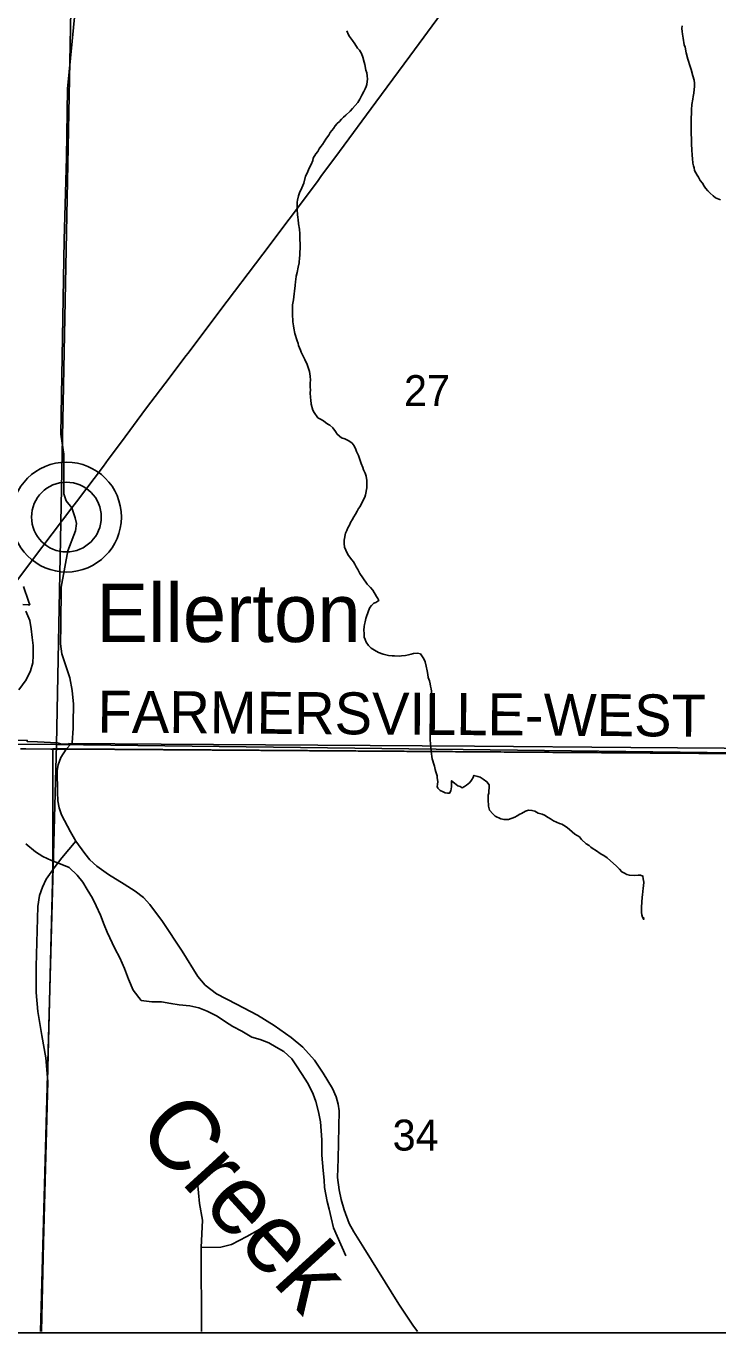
# Model space of a CAD drawing. Extents: x 0 to 34, y 0 to 22.
# Drawn here: x 2.988 to 3.924, y 14 to 15.768 of the extents above; entities that cross this region are included whole.
import ezdxf

# ---------------------------------------------------------------- set-up
doc = ezdxf.new("R2010")
doc.units = 0
for name, color, linetype in [('GM_X_County_Road', 7, 'Continuous'), ('GM_X_County_Road_Text', 7, 'Continuous'), ('GM_X_Interchange_Ramps', 7, 'Continuous'), ('GM_X_Interstate_Route', 7, 'Continuous'), ('GM_X_Minor_River', 7, 'Continuous'), ('GM_X_Minor_River_Text', 7, 'Continuous'), ('GM_X_Section', 7, 'Continuous'), ('GM_X_Section_Text', 7, 'Continuous'), ('GM_X_State_Route', 7, 'Continuous'), ('GM_X_State_Shield', 7, 'Continuous'), ('GM_X_Township_Road', 7, 'Continuous'), ('GM_X_Unincorporated', 7, 'Continuous'), ('GM_X_Unincorporated_Location', 7, 'Continuous'), ('GM_X_Unincorporated_Text', 7, 'Continuous'), ('SH_Data', 7, 'Continuous')]:
    doc.layers.add(name, color=color, linetype=linetype)

msp = doc.modelspace()

# ---------------------------------------------------------------- linework, layer by layer
at = {"layer": 'GM_X_County_Road'}
for p, q in [((3.042, 14.7898), (3.0487, 14.797)), ((3.042, 14.7898), (4.0225, 14.783)), ((3.0084, 14.0019), (3.0115, 14.1223))]:
    msp.add_line(p, q, dxfattribs=at)
for points in [[(3.0365, 15.2041), (3.0346, 15.2161), (3.0374, 15.3737), (3.0394, 15.4793), (3.0423, 15.5906), (3.0436, 15.6833), (3.0543, 15.7893), (3.0548, 15.7993)], [(3.0497, 15.1165), (3.042, 15.1261), (3.0389, 15.1356), (3.0389, 15.1892), (3.0365, 15.2041)], [(3.0487, 14.797), (3.05, 14.7984), (3.0515, 14.8181), (3.0516, 14.8251), (3.0519, 14.8508), (3.0503, 14.8692), (3.0469, 14.8864), (3.0363, 14.9191), (3.0351, 14.9255), (3.0345, 14.9323), (3.0348, 14.9583), (3.0352, 15.0093), (3.0444, 15.0583), (3.0547, 15.0852), (3.0558, 15.0952), (3.054, 15.1031), (3.0497, 15.1165)], [(2.9802, 14.7905), (2.9873, 14.7903), (3.0212, 14.7899)], [(3.0212, 14.7899), (3.0242, 14.7899), (3.042, 14.7898)], [(3.0237, 14.6266), (3.0243, 14.6275), (3.0362, 14.643), (3.0549, 14.6653), (3.0478, 14.6779), (3.0356, 14.7011), (3.0323, 14.7106), (3.0309, 14.72), (3.0303, 14.7319), (3.0296, 14.7609), (3.0312, 14.7688), (3.0347, 14.7784), (3.042, 14.7898)], [(3.0115, 14.1223), (3.017, 14.34), (3.0143, 14.3722), (3.0092, 14.4025), (3.0035, 14.435), (3.0012, 14.4605), (3.0015, 14.496), (3.0037, 14.5769), (3.0057, 14.5919), (3.0101, 14.603), (3.015, 14.6139), (3.0237, 14.6266)]]:
    msp.add_lwpolyline(points, dxfattribs=at)
at = {"layer": 'GM_X_Interchange_Ramps'}
for points in [[(2.9842, 15.0102), (2.9911, 14.99), (2.9927, 14.9853), (2.9907, 14.9854), (2.9835, 14.9857)], [(2.9612, 14.8022), (2.9892, 14.8018), (2.9891, 14.8003), (3.0033, 14.8), (3.0297, 14.7986), (3.0297, 14.7986), (3.036, 14.7967), (3.0455, 14.7966), (3.0457, 14.7976), (3.1707, 14.7967), (3.3824, 14.7952), (3.5947, 14.7938), (3.8063, 14.7923), (3.9957, 14.791)]]:
    msp.add_lwpolyline(points, dxfattribs=at)
at = {"layer": 'GM_X_Interstate_Route'}
for points in [[(4.0223, 14.7835), (3.0418, 14.7903), (3.024, 14.7904), (3.0241, 14.628), (3.0168, 14.3406), (3.0082, 14.0019)], [(3.0082, 14.0019), (3.0168, 14.3406), (3.0241, 14.628), (3.024, 14.7904), (3.0418, 14.7903), (4.0223, 14.7835)]]:
    msp.add_lwpolyline(points, dxfattribs=at)
at = {"layer": 'GM_X_Minor_River'}
for points in [[(3.4217, 15.7618), (3.4242, 15.7568), (3.4256, 15.7541), (3.4297, 15.7487), (3.4326, 15.7444), (3.4363, 15.7386), (3.4389, 15.7359), (3.4418, 15.7312), (3.4436, 15.7262), (3.4453, 15.7197), (3.446, 15.7163), (3.4477, 15.7086), (3.4488, 15.7052), (3.4494, 15.7013), (3.4497, 15.6964), (3.4492, 15.6933), (3.4488, 15.6895), (3.4479, 15.6865), (3.4467, 15.6835), (3.4447, 15.6797), (3.4423, 15.6748), (3.4395, 15.6696), (3.4367, 15.6651), (3.4296, 15.6568), (3.4265, 15.6535), (3.4206, 15.6479), (3.4175, 15.6453), (3.4148, 15.6423), (3.412, 15.6394), (3.4089, 15.6364), (3.4061, 15.6334), (3.4038, 15.63), (3.4014, 15.627), (3.3994, 15.6244), (3.3974, 15.621), (3.3955, 15.6184), (3.3935, 15.6154), (3.3911, 15.6117), (3.3887, 15.6083), (3.3867, 15.6053), (3.3844, 15.6023), (3.3824, 15.5989), (3.38, 15.5956), (3.3764, 15.5899), (3.3756, 15.5865), (3.3735, 15.5812), (3.3711, 15.5771), (3.3675, 15.5684), (3.3659, 15.5654), (3.3637, 15.5559), (3.3621, 15.5525), (3.3597, 15.5465), (3.3581, 15.5439), (3.3564, 15.5386), (3.3551, 15.5329), (3.3547, 15.5302), (3.3544, 15.5196), (3.355, 15.5135), (3.3557, 15.5093), (3.356, 15.5066), (3.3566, 15.5008), (3.3579, 15.4936), (3.3581, 15.4871), (3.3584, 15.4837), (3.3584, 15.481), (3.3585, 15.4726), (3.3581, 15.4577), (3.3577, 15.4551), (3.3571, 15.4479), (3.3558, 15.4422), (3.3545, 15.435), (3.3532, 15.43), (3.3527, 15.4255), (3.3523, 15.4228), (3.3518, 15.4175), (3.3512, 15.4099), (3.3507, 15.4061), (3.3497, 15.3981), (3.3484, 15.3913), (3.3481, 15.3791), (3.3489, 15.368), (3.3496, 15.3627), (3.3499, 15.3596), (3.3516, 15.3523), (3.3544, 15.3427), (3.3558, 15.3389), (3.3565, 15.3362), (3.359, 15.3297), (3.3601, 15.327), (3.363, 15.3208), (3.3652, 15.3173), (3.368, 15.3104), (3.3712, 15.3012), (3.3722, 15.2947), (3.3725, 15.2893), (3.3724, 15.2855), (3.3722, 15.2802), (3.3725, 15.2756), (3.3724, 15.2726), (3.3726, 15.2653), (3.3729, 15.2627)], [(3.8755, 15.7687), (3.8754, 15.7653), (3.8757, 15.7611), (3.8759, 15.7573), (3.8769, 15.7519), (3.8782, 15.7431), (3.8797, 15.7397), (3.881, 15.732), (3.8835, 15.7236), (3.8866, 15.7136), (3.888, 15.7097), (3.8901, 15.7013), (3.8919, 15.6951), (3.8925, 15.6913), (3.8924, 15.6871), (3.8914, 15.6776), (3.8905, 15.6731), (3.8901, 15.6697), (3.8887, 15.6624), (3.8882, 15.6552), (3.8878, 15.6392), (3.8879, 15.6316), (3.8879, 15.6289), (3.888, 15.6205), (3.8883, 15.6179), (3.8885, 15.611), (3.8885, 15.6083), (3.8887, 15.6015), (3.8892, 15.5931), (3.8895, 15.5892), (3.8901, 15.5828), (3.8908, 15.5793), (3.8918, 15.5766), (3.8925, 15.5728), (3.8962, 15.5666), (3.8976, 15.5639), (3.9002, 15.5596), (3.9031, 15.5558), (3.9053, 15.5519), (3.9071, 15.5492), (3.9105, 15.5453), (3.9134, 15.5422), (3.9176, 15.5386), (3.9209, 15.5359), (3.9277, 15.5331)], [(3.3729, 15.2627), (3.3735, 15.2569), (3.3756, 15.2485), (3.3774, 15.2454), (3.3826, 15.2384), (3.3863, 15.2364), (3.3901, 15.234), (3.3931, 15.2321), (3.3961, 15.2297), (3.3987, 15.2285), (3.4028, 15.2246), (3.4065, 15.2199), (3.4087, 15.2164), (3.4146, 15.211), (3.4192, 15.2097), (3.4245, 15.2073), (3.429, 15.2041), (3.4319, 15.2002), (3.4341, 15.1956), (3.4351, 15.1929), (3.4377, 15.1871), (3.4412, 15.1764), (3.4437, 15.171), (3.4444, 15.1679), (3.4466, 15.1633), (3.448, 15.1595), (3.449, 15.1537), (3.4487, 15.1434), (3.447, 15.1343), (3.4461, 15.1309), (3.4441, 15.1268), (3.4397, 15.1185), (3.4377, 15.1155), (3.4357, 15.1121), (3.4337, 15.108), (3.4313, 15.1042), (3.4289, 15.1001), (3.4269, 15.0967), (3.4253, 15.093), (3.4233, 15.0892), (3.4217, 15.0858), (3.4201, 15.082), (3.4183, 15.0729), (3.4182, 15.068), (3.4185, 15.0634), (3.4203, 15.0592), (3.4224, 15.0553), (3.4243, 15.0522), (3.4287, 15.046), (3.4309, 15.0433), (3.4327, 15.0402), (3.4345, 15.0367), (3.4367, 15.0329), (3.4396, 15.0278), (3.4433, 15.0216), (3.4492, 15.0131), (3.454, 15.0088), (3.457, 15.0049), (3.4621, 14.9964), (3.4639, 14.9937), (3.465, 14.991), (3.4611, 14.9884), (3.4584, 14.9874), (3.4553, 14.9844), (3.4529, 14.9814), (3.4513, 14.9769), (3.4476, 14.9667), (3.4467, 14.9621), (3.4459, 14.9587), (3.4454, 14.9557), (3.4449, 14.9511), (3.4452, 14.9465), (3.4454, 14.9416), (3.4465, 14.9381), (3.4479, 14.9347), (3.4512, 14.9304), (3.4549, 14.9265), (3.4591, 14.9237), (3.4647, 14.9209), (3.4711, 14.9185), (3.4783, 14.9168), (3.4833, 14.9163), (3.4863, 14.9162), (3.4928, 14.9157), (3.4958, 14.916), (3.5012, 14.9166), (3.5054, 14.9176), (3.5089, 14.9183), (3.5119, 14.9194), (3.5173, 14.92), (3.5215, 14.9191), (3.5259, 14.9122), (3.5277, 14.9083), (3.529, 14.9022), (3.5304, 14.8961), (3.5314, 14.8911), (3.5321, 14.8869), (3.5335, 14.8823), (3.5345, 14.8781), (3.5352, 14.875), (3.5359, 14.8716)], [(2.978, 14.87), (2.9879, 14.8838), (2.9939, 14.8958), (2.9969, 14.9068), (2.9975, 14.9166), (2.9971, 14.93), (2.9959, 14.941), (2.9947, 14.9528), (2.9927, 14.9639), (2.9874, 14.9766)], [(3.5359, 14.8716), (3.5362, 14.8685), (3.5364, 14.8624), (3.5362, 14.8555), (3.5357, 14.8517), (3.5354, 14.8392), (3.5353, 14.8361), (3.5349, 14.8331), (3.5344, 14.8156), (3.5347, 14.811), (3.5345, 14.8057), (3.5348, 14.8022), (3.5354, 14.7931), (3.536, 14.7866), (3.5363, 14.7835), (3.5369, 14.7801), (3.5372, 14.7767), (3.5383, 14.774), (3.539, 14.7709), (3.5404, 14.7671), (3.5414, 14.7625), (3.5425, 14.759), (3.5439, 14.7536), (3.5442, 14.751), (3.5448, 14.746), (3.5447, 14.7422), (3.5443, 14.7395), (3.545, 14.7369), (3.5483, 14.7341), (3.5521, 14.7321), (3.5551, 14.7309), (3.5581, 14.7304), (3.5608, 14.7304), (3.5628, 14.7334), (3.5633, 14.7391), (3.5635, 14.7471), (3.5676, 14.7439), (3.5721, 14.7404), (3.5751, 14.7392), (3.5781, 14.7376), (3.5812, 14.7394), (3.584, 14.7412), (3.5882, 14.7446), (3.5906, 14.7479), (3.5926, 14.7517), (3.5938, 14.7543), (3.5991, 14.7531), (3.6021, 14.7518), (3.6063, 14.7491), (3.6115, 14.7459), (3.6145, 14.7416), (3.6144, 14.7374), (3.6139, 14.7333), (3.6138, 14.7302), (3.6133, 14.7276), (3.6131, 14.7192), (3.6134, 14.7154), (3.6137, 14.7127), (3.6151, 14.7073), (3.6195, 14.7023), (3.6225, 14.6991), (3.6304, 14.6955), (3.6346, 14.6947), (3.6376, 14.6946), (3.6407, 14.6949), (3.6492, 14.6977), (3.6523, 14.6999), (3.6558, 14.7021), (3.6584, 14.7028), (3.6635, 14.7058), (3.6677, 14.7072), (3.6723, 14.7071), (3.6764, 14.7058), (3.681, 14.7034), (3.6862, 14.7018), (3.6893, 14.7006), (3.6945, 14.6974), (3.6975, 14.6958), (3.7016, 14.693), (3.7096, 14.6894), (3.713, 14.6882), (3.7171, 14.6858), (3.7205, 14.6834), (3.7231, 14.6811), (3.7305, 14.6748), (3.7365, 14.6712), (3.7395, 14.6677), (3.7458, 14.6619), (3.7496, 14.6595), (3.7522, 14.6571), (3.7552, 14.6548), (3.7582, 14.6532), (3.766, 14.6476), (3.7698, 14.646), (3.7743, 14.6429), (3.7788, 14.639), (3.7862, 14.6319), (3.7907, 14.6276), (3.794, 14.6237), (3.7978, 14.6221), (3.8008, 14.6205)], [(3.4205, 14.1042), (3.4038, 14.142), (3.4004, 14.1557), (3.398, 14.1672), (3.3953, 14.1776), (3.3933, 14.1871), (3.3916, 14.1967), (3.3911, 14.2066), (3.39, 14.2199), (3.3882, 14.2405), (3.3878, 14.2515), (3.388, 14.261), (3.3872, 14.2736), (3.386, 14.2854), (3.3834, 14.2992), (3.3799, 14.313), (3.3764, 14.323), (3.3696, 14.3372), (3.3604, 14.3508), (3.3539, 14.3612), (3.3473, 14.3709), (3.3365, 14.3807), (3.326, 14.3867), (3.3163, 14.3923), (3.3046, 14.3972), (3.2933, 14.4002), (3.2798, 14.4082), (3.2674, 14.4146), (3.2577, 14.421), (3.2465, 14.4285), (3.2329, 14.4354), (3.2213, 14.4399), (3.2095, 14.4425), (3.1951, 14.444), (3.1837, 14.4459), (3.1709, 14.4478), (3.1579, 14.4481), (3.1435, 14.4497), (3.1325, 14.4637), (3.1264, 14.4787), (3.1207, 14.4933), (3.1146, 14.5075), (3.1077, 14.5203), (3.0973, 14.5423), (3.0934, 14.5522), (3.0884, 14.5653), (3.0827, 14.578), (3.0776, 14.5881), (3.0703, 14.6001), (3.0645, 14.6097), (3.0568, 14.6195), (3.046, 14.6296), (3.034, 14.6349), (3.0219, 14.6391), (3.0103, 14.6447), (3.0005, 14.6511), (2.9875, 14.6617)], [(3.8008, 14.6205), (3.8042, 14.6193), (3.8114, 14.6191), (3.816, 14.6194), (3.8191, 14.6193), (3.8225, 14.6181), (3.8231, 14.6146), (3.8238, 14.61), (3.8233, 14.6051), (3.8228, 14.6017), (3.8222, 14.5929), (3.8217, 14.5895), (3.8212, 14.5827), (3.8206, 14.5762), (3.8205, 14.5724), (3.8208, 14.569), (3.8211, 14.5659), (3.8218, 14.5625), (3.8236, 14.5594), (3.8233, 14.5624)]]:
    msp.add_lwpolyline(points, dxfattribs=at)
at = {"layer": 'GM_X_Section'}
msp.add_lwpolyline([(3.0481, 15.7894), (4.0274, 15.7833), (4.0198, 14.784), (3.0289, 14.7963)], close=True, dxfattribs=at)
msp.add_lwpolyline([(3.0071, 14.0019), (3.0289, 14.7963), (4.0198, 14.784), (4.0152, 14.0019)], dxfattribs=at)
at = {"layer": 'GM_X_State_Route'}
for points in [[(3.3868, 15.5648), (3.412, 15.5986), (3.4609, 15.6653), (3.5071, 15.7277), (3.5501, 15.7858)], [(3.2027, 15.3205), (3.2083, 15.3278), (3.2498, 15.3832), (3.3082, 15.4598), (3.3438, 15.5072), (3.382, 15.5583), (3.3868, 15.5648)], [(3.0989, 15.1817), (3.117, 15.2059), (3.1495, 15.2502), (3.1825, 15.2937), (3.2027, 15.3205)], [(3.0559, 15.1247), (3.0923, 15.1728), (3.0989, 15.1817)], [(2.9552, 14.991), (2.9965, 15.0459), (3.0497, 15.1165), (3.0559, 15.1247)]]:
    msp.add_lwpolyline(points, dxfattribs=at)
at = {"layer": 'GM_X_State_Shield'}
msp.add_lwpolyline([(2.1171, 15.7957), (2.1171, 14.8034), (3.0289, 14.7963), (3.0481, 15.7894)], close=True, dxfattribs=at)
msp.add_lwpolyline([(3.0071, 14.0019), (3.0289, 14.7963), (2.1171, 14.8034), (2.1171, 14.0019)], dxfattribs=at)
at = {"layer": 'GM_X_Township_Road'}
for points in [[(3.5176, 14.0019), (3.511, 14.0106), (3.4922, 14.0389), (3.445, 14.1149), (3.4311, 14.1366), (3.4251, 14.1478), (3.4181, 14.1664), (3.414, 14.1806), (3.4113, 14.1936), (3.4093, 14.2102), (3.4102, 14.2353), (3.4116, 14.3006), (3.4102, 14.3094), (3.4075, 14.3193), (3.4025, 14.3308), (3.3899, 14.3515), (3.3782, 14.3689), (3.3622, 14.3865), (3.3463, 14.3997), (3.3236, 14.4158), (3.3007, 14.43), (3.2724, 14.4446), (3.2453, 14.459), (3.23, 14.4706), (3.2203, 14.4823), (3.1988, 14.5164), (3.1723, 14.5567), (3.1554, 14.5799), (3.1464, 14.5891), (3.1354, 14.5979), (3.1203, 14.6074), (3.0994, 14.6202), (3.0833, 14.6315), (3.0742, 14.6403), (3.067, 14.6487), (3.0549, 14.6653)], [(3.2253, 14.0019), (3.2248, 14.1156), (3.2263, 14.1523), (3.2224, 14.175), (3.2197, 14.2041)], [(3.2248, 14.1156), (3.2512, 14.1159), (3.2657, 14.1196), (3.2866, 14.1305), (3.3042, 14.1405)]]:
    msp.add_lwpolyline(points, dxfattribs=at)
at = {"layer": 'GM_X_Unincorporated'}
for radius in [0.0744, 0.0472]:
    msp.add_circle((3.0423, 15.104), radius, dxfattribs=at)
at = {"layer": 'GM_X_Unincorporated_Location'}
msp.add_line((3.0423, 15.104), (3.0423, 15.104), dxfattribs=at)
at = {"layer": 'SH_Data'}
msp.add_line((2, 14), (9, 14), dxfattribs=at)

# ---------------------------------------------------------------- texts
at = {"layer": 'GM_X_County_Road_Text'}
msp.add_text('FARMERSVILLE-WEST', height=0.056818, rotation=359.6113, dxfattribs=at).set_placement((3.0843, 14.8123))
at = {"layer": 'GM_X_Minor_River_Text'}
msp.add_text('Creek', height=0.0947, rotation=312.3695, dxfattribs=at).set_placement((3.1348, 14.2709))
at = {"layer": 'GM_X_Section_Text'}
for s, p in [('27', (3.4992, 15.2542)), ('34', (3.4838, 14.2467))]:
    msp.add_text(s, height=0.04186, rotation=0, dxfattribs=at).set_placement(p)
at = {"layer": 'GM_X_Unincorporated_Text'}
msp.add_text('Ellerton', height=0.07898, rotation=0, dxfattribs=at).set_placement((3.0825, 14.9349))

doc.saveas('drawing.dxf')
